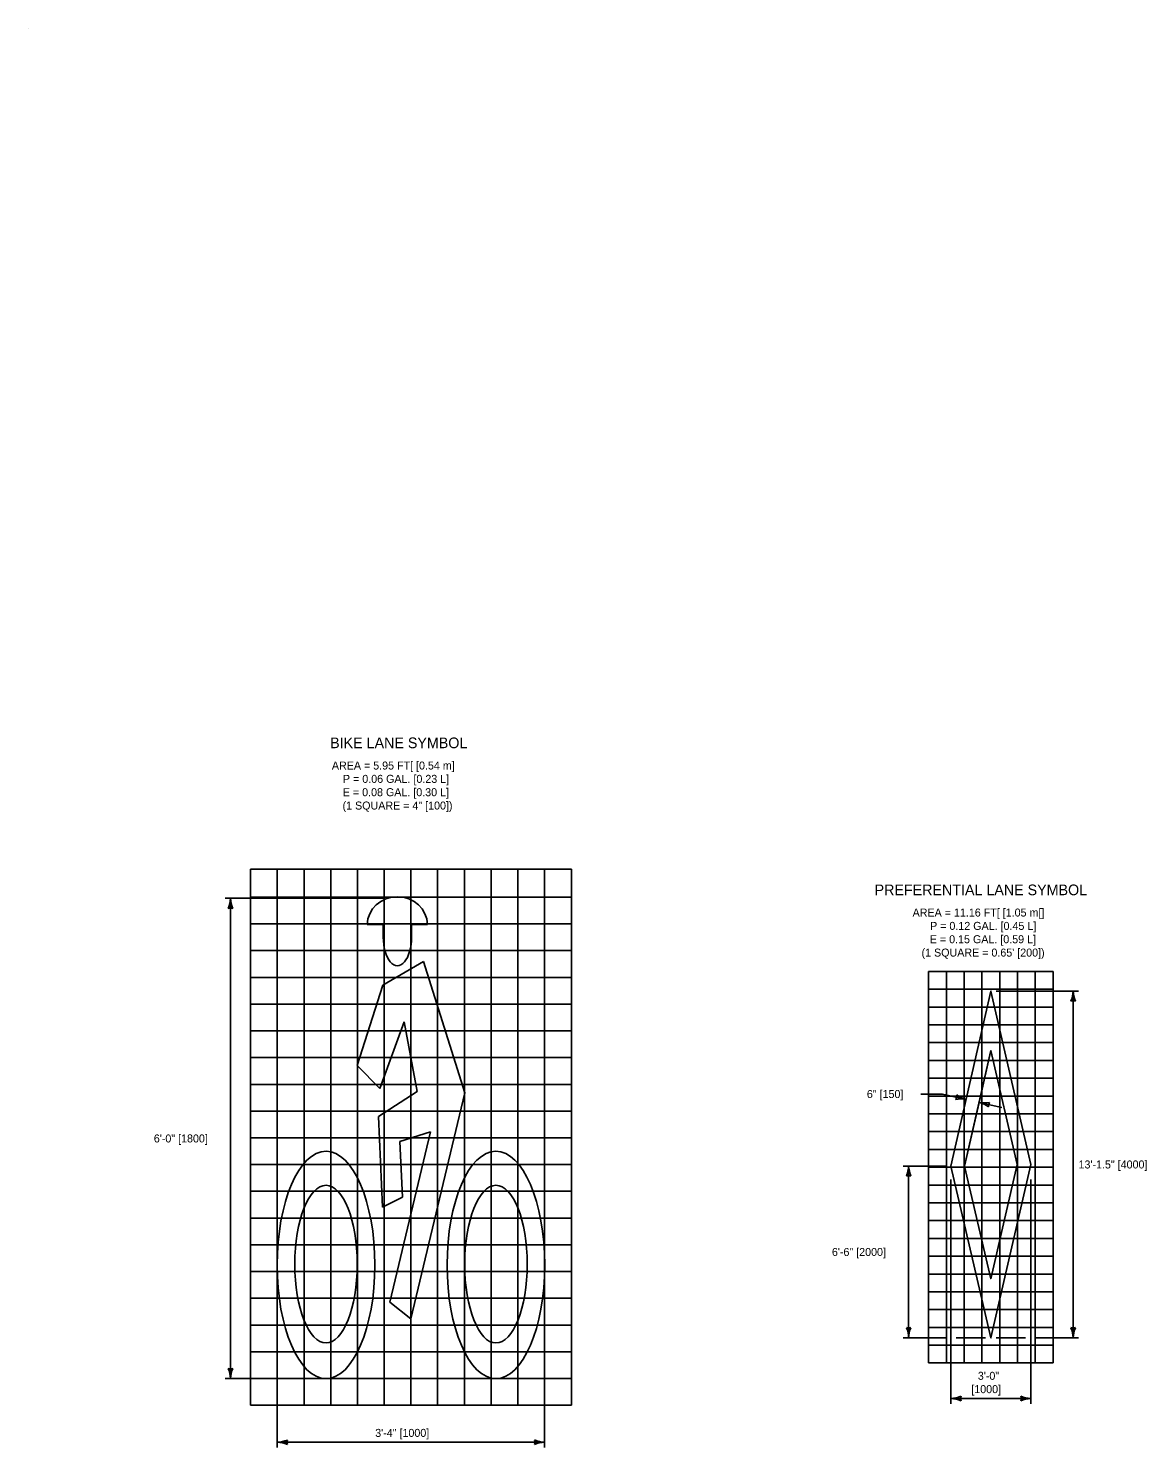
# Model space of a CAD drawing. Extents: x 49948.7 to 50021, y 49977 to 50017.6.
# Drawn here: x 49999.02 to 50007.41, y 49976.96 to 49987.6 of the extents above; entities that cross this region are included whole.
import ezdxf

# ---------------------------------------------------------------- set-up
doc = ezdxf.new("R2010")
doc.units = 0
for name, color, linetype in [('Level 1', 7, 'Continuous'), ('Level 2', 7, 'Continuous'), ('Level 3', 7, 'Continuous'), ('Level 9', 7, 'Continuous')]:
    doc.layers.add(name, color=color, linetype=linetype)

msp = doc.modelspace()

# ---------------------------------------------------------------- linework, layer by layer
at = {"layer": 'Level 1'}
for p, q in [((49999.024, 49987.599), (49999.024, 49987.599)), ((50001.565, 49980.882), (50001.685, 49980.882)), ((50001.685, 49980.882), (50001.685, 49980.788)), ((50001.897, 49980.788), (50001.897, 49980.882)), ((50001.897, 49980.882), (50002.017, 49980.882)), ((50001.681, 49980.428), (50001.988, 49980.606)), ((50001.988, 49980.606), (50002.298, 49979.622)), ((50001.489, 49979.826), (50001.681, 49980.428)), ((50005.941, 49979.072), (50006.241, 49980.384)), ((50006.241, 49980.384), (50006.541, 49979.084)), ((50001.842, 49980.153), (50001.659, 49979.653)), ((50001.939, 49979.632), (50001.842, 49980.153)), ((50006.044, 49979.072), (50006.241, 49979.938)), ((50006.241, 49979.938), (50006.438, 49979.084)), ((50001.659, 49979.653), (50001.489, 49979.826)), ((50001.649, 49979.443), (50001.939, 49979.632)), ((50002.298, 49979.622), (50001.893, 49977.928)), ((50001.679, 49978.764), (50001.649, 49979.443)), ((50001.734, 49978.051), (50002.039, 49979.329)), ((50002.039, 49979.329), (50001.81, 49979.255)), ((50001.81, 49979.255), (50001.829, 49978.839)), ((50005.941, 49979.072), (50006.241, 49977.784)), ((50006.044, 49979.072), (50006.24, 49978.227)), ((50006.438, 49979.084), (50006.24, 49978.227)), ((50006.541, 49979.084), (50006.241, 49977.784)), ((50001.829, 49978.839), (50001.679, 49978.764)), ((50001.893, 49977.928), (50001.734, 49978.051))]:
    msp.add_line(p, q, dxfattribs=at)
for points in [[(50005.941, 49979.072), (50006.241, 49977.784), (50006.541, 49979.084), (50006.241, 49980.384), (50005.941, 49979.072)], [(50006.153, 49979.549), (50006.241, 49979.938), (50006.438, 49979.084), (50006.24, 49978.227), (50006.044, 49979.072), (50006.153, 49979.549)]]:
    msp.add_lwpolyline(points, dxfattribs=at)
for centre, major_axis, ratio, start_param, end_param in [((50001.791, 49980.877), (0.226, 0), 0.94434, 0.021961, 3.119631), ((50001.791, 49980.788), (0, 0.215), 0.492624, 1.570796, 4.712389), ((50006.153, 49979.508), (0, 0.0433), 0.068398, 0.279235, 0.283228), ((50006.153, 49979.481), (0, 0.0691), 0.041672, 0.184884, 0.188691)]:
    msp.add_ellipse(centre, major_axis=major_axis, ratio=ratio, start_param=start_param, end_param=end_param, dxfattribs=at)
for centre, major_axis, ratio in [((50001.256, 49978.331), (0, -0.852), 0.430046), ((50001.256, 49978.331), (0, -0.852), 0.430046), ((50002.53, 49978.331), (0, -0.852), 0.429701), ((50002.53, 49978.331), (0, -0.852), 0.429701), ((50001.256, 49978.337), (0, -0.591), 0.396656), ((50001.256, 49978.337), (0, -0.591), 0.396656), ((50002.53, 49978.337), (0, -0.591), 0.396246), ((50002.53, 49978.337), (0, -0.591), 0.396246)]:
    msp.add_ellipse(centre, major_axis=major_axis, ratio=ratio, dxfattribs=at)
at = {"layer": 'Level 3'}
for p, q in [((50001.694, 49981.079), (50000.5, 49981.079)), ((50000.54, 49977.479), (50000.54, 49981.079)), ((50006.281, 49980.384), (50006.898, 49980.384)), ((50006.858, 49977.784), (50006.858, 49980.384)), ((50005.877, 49979.612), (50005.716, 49979.612)), ((50005.877, 49979.612), (50006.055, 49979.571)), ((50006.153, 49979.549), (50006.322, 49979.511)), ((50005.901, 49979.072), (50005.584, 49979.072)), ((50005.624, 49979.072), (50005.624, 49977.784)), ((50005.941, 49978.972), (50005.941, 49977.29)), ((50006.541, 49978.972), (50006.541, 49977.29)), ((50002.895, 49978.331), (50002.895, 49976.962)), ((50000.89, 49978.265), (50000.89, 49977.546)), ((50005.901, 49977.784), (50005.584, 49977.784)), ((50006.201, 49977.784), (50005.981, 49977.784)), ((50006.281, 49977.784), (50006.501, 49977.784)), ((50006.581, 49977.784), (50006.898, 49977.784)), ((50000.905, 49977.479), (50000.5, 49977.479)), ((50000.89, 49977.413), (50000.89, 49976.962)), ((50005.941, 49977.33), (50006.541, 49977.33)), ((50000.89, 49977.002), (50002.895, 49977.002))]:
    msp.add_line(p, q, dxfattribs=at)
for centre, radius, start, end in [((50000.318, 49981.088), 0.222, 337.4552, 357.6387), ((50000.773, 49981.091), 0.233, 182.8265, 202.0763), ((50000.54, 49980.951), 0.0548, 72.138, 107.8604), ((50006.635, 49980.393), 0.222, 337.456, 357.6395), ((50007.09, 49980.396), 0.233, 182.8273, 202.0772), ((50006.858, 49980.256), 0.0548, 72.1388, 107.8612), ((50005.93, 49979.6), 0.0548, 329.3813, 5.1036), ((50006.113, 49979.786), 0.222, 234.6985, 254.882), ((50006.015, 49979.342), 0.233, 80.0698, 99.3196), ((50006.095, 49979.335), 0.222, 54.6985, 74.882), ((50006.193, 49979.779), 0.233, 260.0698, 279.3196), ((50006.278, 49979.521), 0.0548, 149.3813, 185.1036), ((50005.402, 49979.081), 0.222, 337.456, 357.6395), ((50005.857, 49979.083), 0.233, 182.8273, 202.0772), ((50005.624, 49978.944), 0.0548, 72.1388, 107.8612), ((50005.624, 49977.913), 0.0548, 252.1388, 287.8612), ((50005.392, 49977.773), 0.233, 2.8273, 22.0772), ((50005.846, 49977.775), 0.222, 157.456, 177.6395), ((50006.858, 49977.913), 0.0548, 252.1388, 287.8612), ((50006.625, 49977.773), 0.233, 2.8273, 22.0772), ((50007.08, 49977.775), 0.222, 157.456, 177.6395), ((50000.54, 49977.607), 0.0548, 252.138, 287.8604), ((50000.307, 49977.468), 0.233, 2.8265, 22.0763), ((50000.762, 49977.47), 0.222, 157.4552, 177.6387), ((50005.929, 49977.563), 0.233, 272.8273, 292.0772), ((50005.932, 49977.108), 0.222, 67.456, 87.6395), ((50006.069, 49977.33), 0.0548, 162.1388, 197.8612), ((50006.55, 49977.552), 0.222, 247.456, 267.6395), ((50006.413, 49977.33), 0.0548, 342.1388, 17.8612), ((50006.552, 49977.097), 0.233, 92.8273, 112.0772), ((50000.879, 49977.234), 0.233, 272.8273, 292.0772), ((50000.881, 49976.78), 0.222, 67.456, 87.6395), ((50001.019, 49977.002), 0.0548, 162.1388, 197.8612), ((50002.904, 49977.224), 0.222, 247.456, 267.6395), ((50002.767, 49977.002), 0.0548, 342.1388, 17.8612), ((50002.907, 49976.769), 0.233, 92.8273, 112.0772)]:
    msp.add_arc(centre, radius, start, end, dxfattribs=at)
at = {"layer": 'Level 9'}
for p, q in [((50000.69, 49981.296), (50000.69, 49977.279)), ((50000.69, 49981.296), (50003.096, 49981.296)), ((50000.89, 49981.296), (50000.89, 49977.279)), ((50001.091, 49981.296), (50001.091, 49977.279)), ((50001.291, 49981.296), (50001.291, 49977.279)), ((50001.492, 49981.296), (50001.492, 49977.279)), ((50001.692, 49981.296), (50001.692, 49977.279)), ((50001.893, 49981.296), (50001.893, 49977.279)), ((50002.093, 49981.296), (50002.093, 49977.279)), ((50002.294, 49981.296), (50002.294, 49977.279)), ((50002.494, 49981.296), (50002.494, 49977.279)), ((50002.695, 49981.296), (50002.695, 49977.279)), ((50002.895, 49981.296), (50002.895, 49977.279)), ((50003.096, 49981.296), (50003.096, 49977.279)), ((50000.69, 49981.088), (50003.096, 49981.088)), ((50000.69, 49980.887), (50003.096, 49980.887)), ((50000.69, 49980.687), (50003.096, 49980.687)), ((50000.69, 49980.486), (50003.096, 49980.486)), ((50005.774, 49980.53), (50005.774, 49977.597)), ((50005.774, 49980.53), (50006.708, 49980.53)), ((50005.908, 49980.53), (50005.908, 49977.597)), ((50006.041, 49980.53), (50006.041, 49977.597)), ((50006.174, 49980.53), (50006.174, 49977.597)), ((50006.308, 49980.53), (50006.308, 49977.597)), ((50006.441, 49980.53), (50006.441, 49977.597)), ((50006.574, 49980.53), (50006.574, 49977.597)), ((50006.708, 49980.53), (50006.708, 49977.597)), ((50005.774, 49980.397), (50006.708, 49980.397)), ((50000.69, 49980.286), (50003.096, 49980.286)), ((50005.774, 49980.263), (50006.708, 49980.263)), ((50005.774, 49980.13), (50006.708, 49980.13)), ((50000.69, 49980.085), (50003.096, 49980.085)), ((50005.774, 49979.997), (50006.708, 49979.997)), ((50000.69, 49979.885), (50003.096, 49979.885)), ((50005.774, 49979.863), (50006.708, 49979.863)), ((50005.774, 49979.73), (50006.708, 49979.73)), ((50000.69, 49979.684), (50003.096, 49979.684)), ((50005.774, 49979.597), (50006.708, 49979.597)), ((50000.69, 49979.484), (50003.096, 49979.484)), ((50005.774, 49979.463), (50006.708, 49979.463)), ((50000.69, 49979.284), (50003.096, 49979.284)), ((50005.774, 49979.33), (50006.708, 49979.33)), ((50005.774, 49979.197), (50006.708, 49979.197)), ((50000.69, 49979.083), (50003.096, 49979.083)), ((50005.774, 49979.063), (50006.708, 49979.063)), ((50000.69, 49978.883), (50003.096, 49978.883)), ((50005.774, 49978.93), (50006.708, 49978.93)), ((50005.774, 49978.797), (50006.708, 49978.797)), ((50000.69, 49978.682), (50003.096, 49978.682)), ((50005.774, 49978.663), (50006.708, 49978.663)), ((50005.774, 49978.53), (50006.708, 49978.53)), ((50000.69, 49978.482), (50003.096, 49978.482)), ((50003.096, 49978.485), (50003.096, 49977.279)), ((50005.774, 49978.397), (50006.708, 49978.397)), ((50000.69, 49978.281), (50003.096, 49978.281)), ((50005.774, 49978.263), (50006.708, 49978.263)), ((50005.774, 49978.13), (50006.708, 49978.13)), ((50000.69, 49978.081), (50003.096, 49978.081)), ((50005.774, 49977.997), (50006.708, 49977.997)), ((50000.69, 49977.88), (50003.096, 49977.88)), ((50005.774, 49977.863), (50006.708, 49977.863)), ((50000.69, 49977.68), (50003.096, 49977.68)), ((50005.774, 49977.73), (50006.708, 49977.73)), ((50005.774, 49977.597), (50006.708, 49977.597)), ((50000.69, 49977.48), (50003.096, 49977.48)), ((50000.69, 49977.279), (50003.096, 49977.279))]:
    msp.add_line(p, q, dxfattribs=at)

# ---------------------------------------------------------------- texts
at = {"layer": 'Level 2'}
for s, height, p in [('BIKE LANE SYMBOL', 0.08, (50001.287, 49982.204)), ('AREA = 5.95 FT[ [0.54 m]', 0.06, (50001.3, 49982.044)), ('P = 0.06 GAL. [0.23 L]', 0.06, (50001.383, 49981.944)), ('E = 0.08 GAL. [0.30 L]', 0.06, (50001.382, 49981.844)), ('(1 SQUARE = 4" [100])', 0.06, (50001.38, 49981.744)), ('PREFERENTIAL LANE SYMBOL', 0.08, (50005.369, 49981.102)), ('AREA = 11.16 FT[ [1.05 m[]', 0.06, (50005.654, 49980.942)), ('P = 0.12 GAL. [0.45 L]', 0.06, (50005.785, 49980.842)), ('E = 0.15 GAL. [0.59 L]', 0.06, (50005.783, 49980.742)), ("(1 SQUARE = 0.65' [200])", 0.06, (50005.721, 49980.642)), ('6" [150]', 0.06, (50005.311, 49979.582)), ('6\'-0" [1800]', 0.06, (49999.965, 49979.249)), ('13\'-1.5" [4000]', 0.06, (50006.898, 49979.054)), ('6\'-6" [2000]', 0.06, (50005.049, 49978.398)), ('3\'-0"', 0.06, (50006.143, 49977.47)), ('[1000]', 0.06, (50006.094, 49977.37)), ('3\'-4" [1000]', 0.06, (50001.625, 49977.042))]:
    msp.add_text(s, height=height, dxfattribs=at).set_placement(p)

doc.saveas('drawing.dxf')
